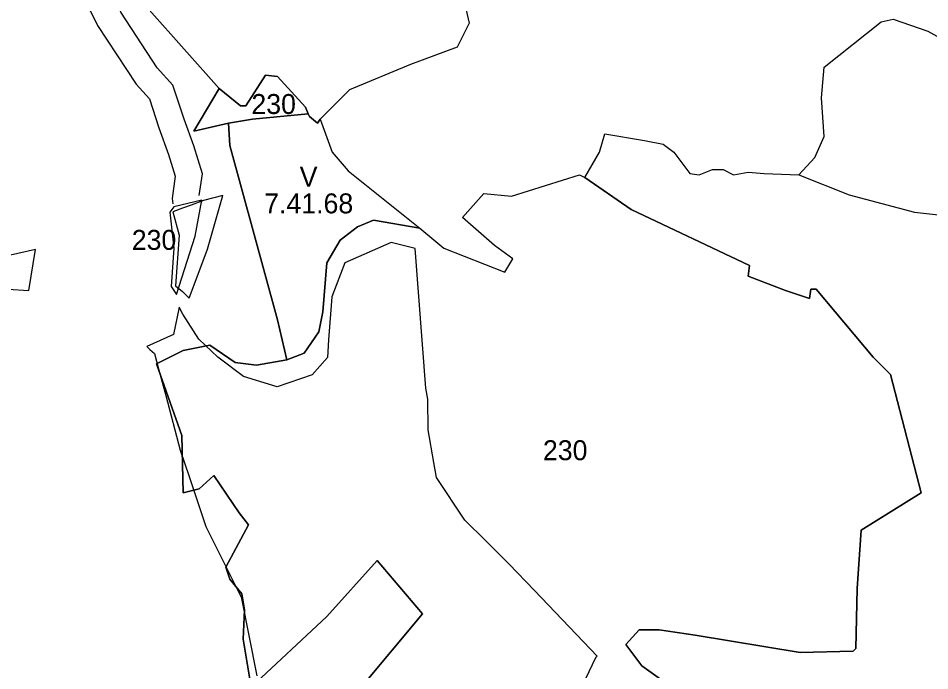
# Model space of a CAD drawing. Extents: x -694504 to -690518, y -983661 to -978958.
# Drawn here: x -692818 to -692133, y -981074 to -980583 of the extents above; entities that cross this region are included whole.
import ezdxf

# ---------------------------------------------------------------- set-up
doc = ezdxf.new("R2010")
doc.units = 0
for name, color, linetype in [('BPEJ', 7, 'Continuous'), ('lokální biocentra', 7, 'Continuous'), ('lokální biokoridory', 7, 'Continuous'), ('třídy přednosti v ochraně ZP', 7, 'Continuous')]:
    doc.layers.add(name, color=color, linetype=linetype)

msp = doc.modelspace()

# ---------------------------------------------------------------- linework, layer by layer
at = {"layer": 'BPEJ'}
for points in [[(-692482.4, -980573.81), (-692479.4, -980586.81), (-692488.4, -980604.81), (-692523.4, -980617.81), (-692569.4, -980636.81), (-692591.4, -980658.81), (-692591.4, -980658.81), (-692593.4, -980661.81), (-692599.4, -980656.81), (-692600.4, -980654.81), (-692602.4, -980649.81), (-692623.4, -980626.81), (-692632.4, -980625.81), (-692647.4, -980648.81), (-692651.4, -980648.81), (-692667.4, -980635.81), (-692746.4, -980546.81)], [(-692746.4, -980546.81), (-692667.4, -980635.81), (-692667.4, -980635.81), (-692686.4, -980667.81), (-692660.4, -980661.81), (-692659.4, -980678.81), (-692623.4, -980809.81), (-692616.4, -980839.81), (-692639.4, -980843.81), (-692655.4, -980841.81), (-692674.4, -980828.81), (-692694.4, -980832.81), (-692714.4, -980842.81), (-692695.4, -980896.81), (-692694.4, -980939.81), (-692682.4, -980936.81), (-692671.4, -980926.81), (-692652.4, -980954.81), (-692645.4, -980963.81), (-692662.4, -980995.81), (-692659.4, -981004.81), (-692650.4, -981015.81), (-692648.4, -981027.81), (-692649.4, -981049.81), (-692643.4, -981085.81), (-692586.4, -981032.81), (-692548.4, -980990.81), (-692514.4, -981030.81), (-692561.4, -981086.81)], [(-692231.4, -980700.81), (-692219.4, -980687.81), (-692212.4, -980671.81), (-692214.4, -980642.81), (-692212.4, -980619.81), (-692169.4, -980585.81), (-692160.4, -980583.81), (-692134.4, -980592.81), (-692094.4, -980614.81), (-692070.4, -980616.81), (-692004.4, -980591.81), (-691991.4, -980592.81), (-691953.4, -980623.81), (-691880.4, -980668.81), (-691797.4, -980699.81), (-691786.4, -980706.81)], [(-692279.4, -981119.81), (-692349.4, -981069.81), (-692361.4, -981053.81), (-692351.4, -981042.81), (-692336.4, -981042.81), (-692309.4, -981046.81), (-692230.4, -981059.81), (-692190.4, -981058.81), (-692188.4, -981056.81), (-692187.4, -981011.81), (-692184.4, -980967.81), (-692139.4, -980939.81), (-692162.4, -980850.81), (-692175.4, -980837.81), (-692218.4, -980786.81), (-692222.4, -980786.81), (-692223.4, -980793.81), (-692241.4, -980787.81), (-692269.4, -980776.81), (-692268.4, -980768.81), (-692357.4, -980726.81), (-692392.4, -980702.81), (-692381.4, -980683.81), (-692377.4, -980669.81), (-692347.4, -980674.81), (-692333.4, -980677.81), (-692325.4, -980683.81), (-692313.4, -980699.81), (-692306.4, -980700.81), (-692296.4, -980696.81), (-692288.4, -980696.81), (-692280.4, -980700.81), (-692269.4, -980698.81), (-692257.4, -980699.81), (-692231.4, -980700.81), (-692231.4, -980700.81), (-692193.4, -980715.81), (-692144.4, -980728.81), (-692126.4, -980730.81)], [(-692694.4, -980832.81), (-692674.4, -980828.81), (-692655.4, -980841.81), (-692639.4, -980843.81), (-692616.4, -980839.81), (-692603.4, -980834.81), (-692592.4, -980818.81), (-692589.4, -980803.81), (-692586.4, -980766.81), (-692576.4, -980749.81), (-692563.4, -980739.81), (-692551.4, -980734.81), (-692516.4, -980740.81), (-692498.4, -980755.81), (-692452.4, -980773.81), (-692446.4, -980763.81), (-692460.4, -980753.81), (-692484.4, -980732.81), (-692468.4, -980714.81), (-692447.4, -980716.81), (-692396.4, -980700.81), (-692392.4, -980702.81), (-692392.4, -980702.81)], [(-692392.4, -980702.81), (-692357.4, -980726.81), (-692268.4, -980768.81), (-692269.4, -980776.81), (-692241.4, -980787.81), (-692223.4, -980793.81), (-692222.4, -980786.81), (-692218.4, -980786.81), (-692175.4, -980837.81), (-692162.4, -980850.81), (-692139.4, -980939.81), (-692184.4, -980967.81), (-692187.4, -981011.81), (-692188.4, -981056.81), (-692190.4, -981058.81), (-692230.4, -981059.81), (-692309.4, -981046.81), (-692336.4, -981042.81), (-692351.4, -981042.81), (-692361.4, -981053.81), (-692349.4, -981069.81), (-692279.4, -981119.81)], [(-692842.4, -980785.81), (-692810.4, -980787.81), (-692805.4, -980756.81), (-692832.4, -980762.81)], [(-692561.4, -981086.81), (-692514.4, -981030.81), (-692548.4, -980990.81), (-692586.4, -981032.81), (-692643.4, -981085.81), (-692649.4, -981049.81), (-692648.4, -981027.81), (-692650.4, -981015.81), (-692659.4, -981004.81), (-692662.4, -980995.81), (-692645.4, -980963.81), (-692652.4, -980954.81), (-692671.4, -980926.81), (-692682.4, -980936.81), (-692694.4, -980939.81), (-692695.4, -980896.81), (-692714.4, -980842.81), (-692694.4, -980832.81)]]:
    msp.add_lwpolyline(points, dxfattribs=at)
for points in [[(-692600.4, -980654.81), (-692642.4, -980658.81), (-692660.4, -980661.81), (-692686.4, -980667.81), (-692667.4, -980635.81), (-692651.4, -980648.81), (-692647.4, -980648.81), (-692632.4, -980625.81), (-692623.4, -980626.81), (-692602.4, -980649.81), (-692600.4, -980654.81)], [(-692591.4, -980658.81), (-692582.4, -980683.81), (-692570.4, -980697.81), (-692516.4, -980740.81), (-692551.4, -980734.81), (-692563.4, -980739.81), (-692576.4, -980749.81), (-692586.4, -980766.81), (-692589.4, -980803.81), (-692592.4, -980818.81), (-692603.4, -980834.81), (-692616.4, -980839.81), (-692623.4, -980809.81), (-692659.4, -980678.81), (-692660.4, -980661.81), (-692642.4, -980658.81), (-692600.4, -980654.81), (-692599.4, -980656.81), (-692593.4, -980661.81), (-692591.4, -980658.81)], [(-692685.4, -980746.81), (-692680.4, -980719.81), (-692701.4, -980724.81), (-692704.4, -980728.81), (-692701.4, -980755.81), (-692703.4, -980784.81), (-692699.4, -980790.81), (-692685.4, -980746.81)]]:
    msp.add_lwpolyline(points, close=True, dxfattribs=at)
at = {"layer": 'lokální biocentra'}
msp.add_lwpolyline([(-692702.18, -980728.57), (-692697.56, -980746.06), (-692700.26, -980784.21), (-692694.89, -980788.38), (-692694.89, -980788.38), (-692689.85, -980793.58), (-692676.03, -980756.67), (-692664.64, -980716.2), (-692679.03, -980720.03), (-692688.42, -980723.49), (-692694.88, -980725.88)], close=True, dxfattribs=at)
msp.add_lwpolyline([(-692402.39, -981101.93), (-692383.73, -981063.02), (-692383, -981062.65), (-692430.3, -981013.26), (-692449.49, -980993.22), (-692456.87, -980985.91), (-692466.85, -980976.01), (-692482.57, -980960.42), (-692503.82, -980928.24), (-692505.8, -980917), (-692510.14, -980892.45), (-692510.5, -980869.45), (-692511.8, -980861), (-692519.93, -980756.1), (-692537.88, -980751.54), (-692572.8, -980766.9), (-692582.74, -980792.5), (-692585.04, -980824.81), (-692585.86, -980837.98), (-692597.41, -980851.13), (-692623.72, -980860.14), (-692648.94, -980852.38), (-692668.26, -980837.85), (-692682.57, -980824.28), (-692694.71, -980805.58), (-692697.43, -980800.3), (-692701.76, -980820.79), (-692721.74, -980829.91), (-692719.48, -980831.98), (-692716.06, -980835.13), (-692712.88, -980846.68), (-692707.37, -980866.68), (-692696.57, -980907.65), (-692689.93, -980927.6), (-692683.74, -980946.21), (-692677.48, -980965.03), (-692658.58, -981002.7), (-692652.78, -981014.25), (-692650.89, -981018.02), (-692639.07, -981077.49)], dxfattribs=at)
at = {"layer": 'lokální biokoridory'}
for points in [[(-692806.8, -980499.66), (-692792.87, -980516.41), (-692781.36, -980542.45), (-692758.83, -980588.42), (-692729.82, -980632.66), (-692719.79, -980643.64), (-692712.67, -980665.45), (-692705.48, -980685.36), (-692700.41, -980701.7), (-692702.76, -980718.64), (-692702.09, -980722.42)], [(-692682.31, -980716.3), (-692679.99, -980700.03), (-692686.52, -980678.99), (-692693.76, -980658.95), (-692702.11, -980633.34), (-692713.98, -980620.35), (-692741.42, -980578.5), (-692763.23, -980534), (-692774.26, -980509), (-692774.26, -980509)]]:
    msp.add_lwpolyline(points, dxfattribs=at)

# ---------------------------------------------------------------- texts
at = {"layer": 'třídy přednosti v ochraně ZP'}
for s, p in [('230', (-692643.1, -980655.01)), ('V', (-692606.78, -980709.71)), ('7.41.68', (-692633.47, -980729.71)), ('230', (-692733.07, -980757.14)), ('230', (-692423.83, -980915.27))]:
    msp.add_text(s, height=15, dxfattribs=at).set_placement(p)

doc.saveas('drawing.dxf')
